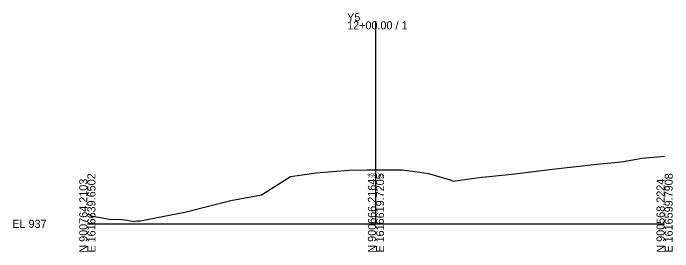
# Model space of a CAD drawing. Extents: x -26 to 1403, y -10 to 4517.
# Drawn here: x -25.7 to 202.8, y 1990.3 to 2072.9 of the extents above; entities that cross this region are included whole.
import ezdxf

# ---------------------------------------------------------------- set-up
doc = ezdxf.new("R2010")
doc.units = 0
for name, color, linetype in [('Exist Cross Section Cell', 7, 'Continuous'), ('Exist XS Center Line Elevation Label', 7, 'Continuous'), ('Exist XS Ground Line', 7, 'Continuous')]:
    doc.layers.add(name, color=color, linetype=linetype)

msp = doc.modelspace()

# ---------------------------------------------------------------- linework, layer by layer
at = {"layer": 'Exist Cross Section Cell'}
for p, q in [((100, 2000), (100, 2070.1)), ((0, 2000), (100, 2000)), ((100, 2000), (200, 2000))]:
    msp.add_line(p, q, dxfattribs=at)
at = {"layer": 'Exist XS Ground Line'}
for p, q in [((185.05, 2021.42), (192.2, 2022.76)), ((192.2, 2022.76), (198.73, 2023.33)), ((198.73, 2023.33), (200, 2023.37)), ((160.11, 2018.84), (176.56, 2020.64)), ((176.56, 2020.64), (185.05, 2021.42)), ((79.33, 2017.6), (90.64, 2018.59)), ((90.64, 2018.59), (97, 2018.65)), ((97, 2018.65), (100.06, 2018.7)), ((100.06, 2018.7), (108.03, 2018.68)), ((108.03, 2018.68), (109.22, 2018.66)), ((109.22, 2018.66), (113.42, 2018.13)), ((113.42, 2018.13), (118.18, 2017.45)), ((148.08, 2017.27), (160.11, 2018.84)), ((60.29, 2010.04), (70.37, 2016.4)), ((70.37, 2016.4), (79.33, 2017.6)), ((118.18, 2017.45), (125.76, 2015.24)), ((131.53, 2015.46), (136.66, 2016.15)), ((136.66, 2016.15), (139.27, 2016.38)), ((139.27, 2016.38), (148.08, 2017.27)), ((125.76, 2015.24), (126.72, 2014.78)), ((126.72, 2014.78), (131.53, 2015.46)), ((49.67, 2008.08), (60.29, 2010.04)), ((34.19, 2004.13), (49.67, 2008.08)), ((0, 2003.47), (1.03, 2003.1)), ((1.03, 2003.1), (1.58, 2002.61)), ((1.58, 2002.61), (3.9, 2002.26)), ((3.9, 2002.26), (8.26, 2001.53)), ((18.47, 2001), (34.19, 2004.13)), ((8.26, 2001.53), (10.92, 2001.56)), ((10.92, 2001.56), (13.93, 2001.31)), ((13.93, 2001.31), (15.97, 2000.78)), ((15.97, 2000.78), (17.21, 2001.01)), ((17.21, 2001.01), (18.47, 2001))]:
    msp.add_line(p, q, dxfattribs=at)

# ---------------------------------------------------------------- texts
at = {"layer": 'Exist Cross Section Cell'}
for s, p in [('Y5', (90, 2070.1)), ('12+00.00 / 1', (90, 2067.3)), ('EL 937', (-26, 1998.6))]:
    msp.add_text(s, height=2.8, dxfattribs=at).set_placement(p)
for s, p in [('E 1616639.6502', (2.8, 1990)), ('E 1616619.7205', (102.8, 1990)), ('E 1616599.7908', (202.8, 1990)), ('N 900764.2103', (0, 1990)), ('N 900666.2164', (100, 1990)), ('N 900568.2224', (200, 1990))]:
    msp.add_text(s, height=2.8, rotation=90, dxfattribs=at).set_placement(p)
at = {"layer": 'Exist XS Center Line Elevation Label'}
msp.add_text('955.70', height=1.25, dxfattribs=at).set_placement((97.05, 2016.07))

doc.saveas('drawing.dxf')
